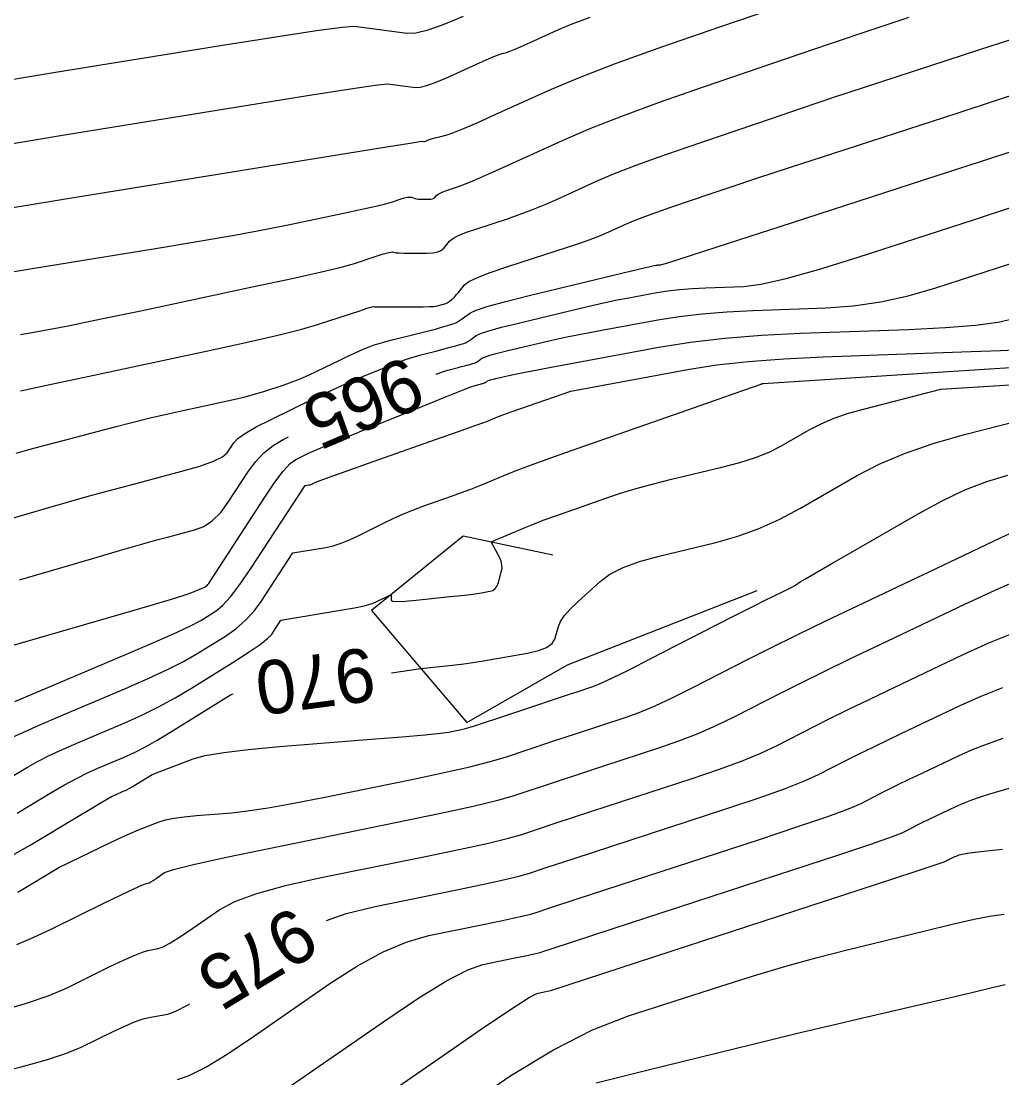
# Model space of a CAD drawing. Extents: x 2175772 to 2185556, y 721391 to 722853.
# Drawn here: x 2178632.3 to 2178683.6, y 721837.5 to 721892.9 of the extents above; entities that cross this region are included whole.
import ezdxf

# ---------------------------------------------------------------- set-up
doc = ezdxf.new("R2010")
doc.units = 0
for name, color, linetype in [('DT_X_Contour_Major', 7, 'Continuous'), ('DT_X_Contour_Minor', 7, 'Continuous'), ('SV_X_Break_Lines', 7, 'Continuous')]:
    doc.layers.add(name, color=color, linetype=linetype)

msp = doc.modelspace()

# ---------------------------------------------------------------- linework, layer by layer
at = {"layer": 'DT_X_Contour_Major'}
for points in [[(2178630.08, 721879.492), (2178632.733, 721879.933), (2178639.3, 721880.999), (2178641.587, 721881.377), (2178643.523, 721881.711), (2178645.106, 721882.002), (2178646.338, 721882.248), (2178649.155, 721882.848), (2178650.103, 721883.053), (2178650.836, 721883.217), (2178651.353, 721883.342), (2178651.655, 721883.426), (2178652.172, 721883.596), (2178652.35, 721883.65), (2178652.499, 721883.681), (2178652.616, 721883.691), (2178652.703, 721883.68), (2178652.895, 721883.62), (2178652.973, 721883.6), (2178653.065, 721883.586), (2178653.169, 721883.578), (2178653.285, 721883.575), (2178653.614, 721883.576), (2178653.727, 721883.582), (2178653.818, 721883.6), (2178653.888, 721883.63), (2178653.937, 721883.671), (2178654.039, 721883.798), (2178654.099, 721883.849), (2178654.204, 721883.905), (2178654.354, 721883.967), (2178654.549, 721884.034), (2178655.126, 721884.222), (2178655.457, 721884.347), (2178656.014, 721884.583), (2178656.798, 721884.929), (2178657.81, 721885.386), (2178660.81, 721886.75), (2178662.103, 721887.304), (2178663.734, 721887.94), (2178665.702, 721888.659), (2178668.007, 721889.462), (2178674.604, 721891.713), (2178676.882, 721892.488), (2178678.768, 721893.126)], [(2178653.993, 721874.416), (2178654.336, 721874.541), (2178654.617, 721874.628), (2178655.148, 721874.761), (2178655.332, 721874.807), (2178655.486, 721874.847), (2178655.611, 721874.88), (2178655.706, 721874.906), (2178655.919, 721874.966), (2178655.998, 721874.993), (2178656.074, 721875.026), (2178656.146, 721875.066), (2178656.215, 721875.114), (2178656.397, 721875.249), (2178656.533, 721875.312), (2178656.805, 721875.4), (2178657.215, 721875.511), (2178657.76, 721875.647), (2178659.397, 721876.042), (2178660.068, 721876.196), (2178660.853, 721876.363), (2178661.751, 721876.541), (2178662.763, 721876.731), (2178665.615, 721877.255), (2178666.729, 721877.433), (2178667.933, 721877.575), (2178669.227, 721877.68), (2178670.61, 721877.75), (2178674.42, 721877.886), (2178675.851, 721877.99), (2178677.288, 721878.199), (2178678.73, 721878.512), (2178680.177, 721878.931), (2178684.044, 721880.188)], [(2178651.666, 721858.763), (2178653.199, 721858.988), (2178655.021, 721859.179), (2178655.443, 721859.229), (2178655.927, 721859.298), (2178656.473, 721859.385), (2178657.082, 721859.49), (2178658.79, 721859.797), (2178659.359, 721859.929), (2178659.786, 721860.094), (2178660.07, 721860.293), (2178660.212, 721860.525), (2178660.402, 721861.191), (2178660.519, 721861.459), (2178660.727, 721861.764), (2178661.027, 721862.108), (2178661.419, 721862.488), (2178662.585, 721863.554), (2178663.106, 721863.937), (2178663.796, 721864.286), (2178664.655, 721864.601), (2178665.682, 721864.882), (2178668.647, 721865.588), (2178669.758, 721865.899), (2178670.866, 721866.303), (2178671.972, 721866.799), (2178673.076, 721867.389), (2178676.017, 721869.084), (2178677.198, 721869.696), (2178678.536, 721870.259), (2178680.03, 721870.776), (2178681.681, 721871.244), (2178689.749, 721873.317)], [(2178632.176, 721863.641), (2178636.07, 721864.777), (2178637.411, 721865.166), (2178638.512, 721865.482), (2178639.375, 721865.725), (2178639.998, 721865.894), (2178641.34, 721866.249), (2178641.828, 721866.439), (2178642.286, 721866.744), (2178642.715, 721867.164), (2178643.113, 721867.699), (2178644.135, 721869.277), (2178644.538, 721869.828), (2178644.98, 721870.296), (2178645.461, 721870.682), (2178645.981, 721870.985), (2178646.269, 721871.125)], [(2178648.253, 721845.79), (2178649.292, 721846.147), (2178650.801, 721846.518), (2178654.997, 721847.372), (2178656.417, 721847.666), (2178657.531, 721847.91), (2178658.339, 721848.103), (2178658.841, 721848.245), (2178659.771, 721848.556), (2178661.226, 721849.036), (2178669.172, 721851.633), (2178670.874, 721852.202), (2178672.251, 721852.691), (2178673.302, 721853.1), (2178674.028, 721853.429), (2178675.529, 721854.198), (2178676.15, 721854.512), (2178676.89, 721854.877), (2178677.747, 721855.292), (2178678.722, 721855.757), (2178681.478, 721857.067), (2178682.547, 721857.544), (2178683.686, 721857.995)], [(2178632.05, 721851.416), (2178633.873, 721852.51), (2178634.536, 721852.896), (2178635.157, 721853.234), (2178635.737, 721853.525), (2178636.275, 721853.768), (2178637.655, 721854.352), (2178638.193, 721854.597), (2178638.771, 721854.892), (2178639.391, 721855.239), (2178640.051, 721855.638), (2178643.226, 721857.615), (2178643.363, 721857.667)], [(2178662.38, 721837.287), (2178663.499, 721837.566), (2178665.029, 721837.944), (2178669.656, 721839.086), (2178671.375, 721839.507), (2178673.064, 721839.915), (2178674.721, 721840.309), (2178676.347, 721840.69), (2178680.64, 721841.687), (2178682.066, 721842.02), (2178683.123, 721842.27), (2178683.81, 721842.439)], [(2178630.678, 721837.737), (2178632.273, 721838.124), (2178633.592, 721838.488), (2178634.637, 721838.831), (2178635.406, 721839.152), (2178637.091, 721839.977), (2178637.686, 721840.256), (2178638.208, 721840.473), (2178638.658, 721840.627), (2178639.034, 721840.72), (2178639.941, 721840.885), (2178640.37, 721841.03), (2178640.979, 721841.343), (2178641.107, 721841.421)]]:
    msp.add_lwpolyline(points, dxfattribs=at)
at = {"layer": 'DT_X_Contour_Minor'}
for points in [[(2178631.516, 721883.086), (2178635.333, 721883.715), (2178651.302, 721886.306), (2178652.745, 721886.539), (2178653.232, 721886.615), (2178653.359, 721886.599), (2178653.381, 721886.6), (2178653.411, 721886.607), (2178653.45, 721886.621), (2178653.498, 721886.641), (2178653.637, 721886.704), (2178653.705, 721886.73), (2178653.806, 721886.76), (2178653.938, 721886.796), (2178654.103, 721886.836), (2178654.586, 721886.951), (2178654.881, 721887.05), (2178655.403, 721887.263), (2178656.154, 721887.59), (2178657.132, 721888.03), (2178660.044, 721889.354), (2178661.415, 721889.93), (2178663.341, 721890.665), (2178665.823, 721891.559), (2178668.861, 721892.611), (2178682.751, 721897.348)], [(2178630.69, 721889.673), (2178633.959, 721890.212), (2178642.71, 721891.632), (2178645.608, 721892.095), (2178647.739, 721892.418), (2178649.102, 721892.601), (2178649.699, 721892.644), (2178650.775, 721892.506), (2178652.467, 721892.281), (2178652.938, 721892.299), (2178653.589, 721892.453), (2178654.42, 721892.745), (2178655.431, 721893.173)], [(2178631.103, 721886.38), (2178634.646, 721886.963), (2178644.13, 721888.503), (2178647.256, 721889.007), (2178649.52, 721889.362), (2178650.924, 721889.57), (2178651.466, 721889.63), (2178652.382, 721889.511), (2178652.913, 721889.44), (2178653.162, 721889.45), (2178653.509, 721889.534), (2178653.955, 721889.692), (2178654.501, 721889.923), (2178656.087, 721890.639), (2178656.618, 721890.876), (2178657.023, 721891.052), (2178657.301, 721891.165), (2178657.452, 721891.217), (2178657.687, 721891.272), (2178657.83, 721891.321), (2178658.084, 721891.424), (2178658.448, 721891.583), (2178658.923, 721891.796), (2178660.337, 721892.44), (2178661.036, 721892.731), (2178662.071, 721893.122)], [(2178632.236, 721876.492), (2178633.319, 721876.682), (2178634.728, 721876.953), (2178636.463, 721877.305), (2178638.525, 721877.738), (2178644.457, 721879.001), (2178646.454, 721879.432), (2178647.998, 721879.778), (2178649.087, 721880.04), (2178649.722, 721880.217), (2178650.811, 721880.577), (2178651.174, 721880.693), (2178651.446, 721880.772), (2178651.626, 721880.814), (2178651.716, 721880.819), (2178651.833, 721880.783), (2178651.914, 721880.771), (2178652.071, 721880.762), (2178652.302, 721880.757), (2178652.607, 721880.756), (2178653.523, 721880.758), (2178653.837, 721880.775), (2178654.091, 721880.825), (2178654.286, 721880.908), (2178654.422, 721881.024), (2178654.706, 721881.377), (2178654.875, 721881.518), (2178655.168, 721881.674), (2178655.585, 721881.846), (2178656.126, 721882.034), (2178657.736, 721882.557), (2178658.357, 721882.771), (2178659.012, 721883.02), (2178659.702, 721883.305), (2178660.427, 721883.625), (2178662.406, 721884.525), (2178663.259, 721884.89), (2178664.335, 721885.309), (2178665.633, 721885.784), (2178667.154, 721886.313), (2178671.506, 721887.798), (2178673.141, 721888.353), (2178674.785, 721888.903), (2178676.437, 721889.45), (2178678.096, 721889.993), (2178682.532, 721891.435), (2178684.055, 721891.931)], [(2178632.232, 721873.544), (2178633.775, 721873.878), (2178635.821, 721874.315), (2178641.949, 721875.619), (2178644.037, 721876.073), (2178645.707, 721876.456), (2178646.958, 721876.768), (2178647.79, 721877.009), (2178649.997, 721877.737), (2178650.393, 721877.863), (2178650.636, 721877.937), (2178650.728, 721877.959), (2178650.771, 721877.945), (2178650.841, 721877.941), (2178651.021, 721877.938), (2178651.708, 721877.937), (2178652.915, 721877.939), (2178653.321, 721877.942), (2178653.634, 721877.95), (2178653.855, 721877.963), (2178653.983, 721877.981), (2178654.39, 721878.084), (2178654.512, 721878.119), (2178654.546, 721878.131), (2178654.586, 721878.152), (2178654.631, 721878.18), (2178654.681, 721878.215), (2178654.821, 721878.321), (2178654.882, 721878.374), (2178654.96, 721878.454), (2178655.055, 721878.562), (2178655.166, 721878.697), (2178655.484, 721879.094), (2178655.712, 721879.264), (2178656.158, 721879.478), (2178656.822, 721879.735), (2178657.704, 721880.035), (2178660.345, 721880.893), (2178661.257, 721881.195), (2178662.011, 721881.457), (2178662.607, 721881.68), (2178663.045, 721881.863), (2178664.003, 721882.299), (2178664.416, 721882.475), (2178664.936, 721882.679), (2178665.564, 721882.908), (2178666.3, 721883.164), (2178668.407, 721883.883), (2178669.401, 721884.217), (2178670.802, 721884.681), (2178672.612, 721885.274), (2178674.829, 721885.996), (2178681.287, 721888.096), (2178683.505, 721888.817), (2178685.317, 721889.409)], [(2178631.995, 721870.268), (2178632.742, 721870.476), (2178633.586, 721870.705), (2178634.528, 721870.956), (2178637.166, 721871.653), (2178638.127, 721871.901), (2178639.028, 721872.125), (2178639.872, 721872.323), (2178640.657, 721872.497), (2178642.672, 721872.926), (2178643.383, 721873.083), (2178644.005, 721873.233), (2178644.538, 721873.376), (2178644.982, 721873.511), (2178646.047, 721873.863), (2178646.454, 721874.006), (2178646.873, 721874.171), (2178647.306, 721874.358), (2178647.753, 721874.567), (2178648.962, 721875.154), (2178649.377, 721875.354), (2178649.717, 721875.515), (2178649.981, 721875.635), (2178650.17, 721875.716), (2178650.571, 721875.879), (2178650.758, 721875.946), (2178651.021, 721876.027), (2178651.358, 721876.12), (2178651.771, 721876.227), (2178652.969, 721876.527), (2178653.385, 721876.632), (2178653.734, 721876.722), (2178654.016, 721876.797), (2178654.231, 721876.856), (2178654.714, 721876.992), (2178654.892, 721877.052), (2178655.063, 721877.127), (2178655.227, 721877.218), (2178655.384, 721877.325), (2178655.793, 721877.632), (2178656.101, 721877.774), (2178656.718, 721877.972), (2178657.643, 721878.224), (2178658.876, 721878.532), (2178663.796, 721879.719), (2178664.676, 721879.93), (2178665.216, 721880.059), (2178665.418, 721880.106), (2178665.503, 721880.122), (2178665.537, 721880.127), (2178665.573, 721880.132), (2178665.612, 721880.135), (2178665.654, 721880.137), (2178665.768, 721880.141), (2178666.191, 721880.268), (2178667.374, 721880.644), (2178669.316, 721881.271), (2178672.018, 721882.148), (2178680.237, 721884.82), (2178683.058, 721885.738), (2178685.357, 721886.488)], [(2178630.957, 721866.627), (2178633.707, 721867.429), (2178634.741, 721867.727), (2178635.781, 721868.02), (2178636.827, 721868.306), (2178637.878, 721868.588), (2178640.688, 721869.33), (2178641.627, 721869.598), (2178642.334, 721869.847), (2178642.81, 721870.077), (2178643.055, 721870.286), (2178643.401, 721870.82), (2178643.618, 721871.045), (2178644.009, 721871.321), (2178644.576, 721871.647), (2178645.317, 721872.024), (2178647.526, 721873.096), (2178648.314, 721873.474), (2178649.021, 721873.802), (2178649.647, 721874.08), (2178650.192, 721874.31), (2178651.537, 721874.855), (2178652.019, 721875.045), (2178652.456, 721875.203), (2178652.847, 721875.33), (2178653.194, 721875.427), (2178654.058, 721875.644), (2178654.358, 721875.72), (2178654.61, 721875.785), (2178654.813, 721875.838), (2178654.968, 721875.881), (2178655.317, 721875.979), (2178655.445, 721876.022), (2178655.568, 721876.076), (2178655.686, 721876.142), (2178655.8, 721876.219), (2178656.095, 721876.441), (2178656.317, 721876.543), (2178656.762, 721876.686), (2178657.429, 721876.868), (2178658.318, 721877.089), (2178660.987, 721877.734), (2178661.932, 721877.957), (2178662.764, 721878.146), (2178663.484, 721878.3), (2178664.091, 721878.419), (2178665.559, 721878.688), (2178666.133, 721878.78), (2178666.753, 721878.853), (2178667.419, 721878.908), (2178668.132, 721878.943), (2178670.094, 721879.014), (2178671.021, 721879.129), (2178672.331, 721879.421), (2178674.023, 721879.892), (2178676.098, 721880.54), (2178682.14, 721882.504), (2178684.214, 721883.179)], [(2178631.428, 721860.095), (2178633.006, 721860.542), (2178637.525, 721861.86), (2178639.026, 721862.3), (2178640.139, 721862.631), (2178640.863, 721862.854), (2178641.2, 721862.969), (2178641.709, 721863.185), (2178641.876, 721863.26), (2178641.914, 721863.281), (2178641.977, 721863.32), (2178642.005, 721863.344), (2178642.042, 721863.387), (2178642.087, 721863.448), (2178642.141, 721863.527), (2178642.664, 721864.329), (2178645.025, 721867.975), (2178645.546, 721868.746), (2178645.99, 721869.332), (2178646.356, 721869.732), (2178646.645, 721869.946), (2178647.312, 721870.27), (2178647.682, 721870.438), (2178648.293, 721870.698), (2178649.145, 721871.051), (2178650.237, 721871.497), (2178653.469, 721872.808), (2178654.539, 721873.241), (2178655.325, 721873.555), (2178655.825, 721873.751), (2178656.041, 721873.828), (2178656.237, 721873.878), (2178656.305, 721873.895), (2178656.408, 721873.922), (2178656.443, 721873.931), (2178656.522, 721873.954), (2178656.551, 721873.963), (2178656.579, 721873.976), (2178656.606, 721873.99), (2178656.631, 721874.008), (2178656.698, 721874.058), (2178656.749, 721874.081), (2178656.849, 721874.114), (2178657, 721874.155), (2178657.202, 721874.205), (2178657.807, 721874.351), (2178658.204, 721874.435), (2178658.941, 721874.579), (2178660.018, 721874.782), (2178661.436, 721875.044), (2178665.671, 721875.821), (2178667.325, 721876.086), (2178669.113, 721876.296), (2178671.034, 721876.453), (2178673.089, 721876.556), (2178678.746, 721876.759), (2178680.681, 721876.851), (2178682.245, 721876.976), (2178683.436, 721877.133), (2178684.256, 721877.323)], [(2178631.934, 721857.267), (2178637.775, 721859.74), (2178639.255, 721860.374), (2178640.398, 721860.88), (2178641.203, 721861.259), (2178641.672, 721861.509), (2178642.471, 721862.007), (2178642.809, 721862.286), (2178643.225, 721862.751), (2178643.718, 721863.401), (2178644.289, 721864.237), (2178647.133, 721868.572), (2178647.338, 721868.606), (2178647.384, 721868.616), (2178647.433, 721868.632), (2178647.487, 721868.653), (2178647.544, 721868.68), (2178647.701, 721868.76), (2178647.917, 721868.844), (2178648.448, 721869.037), (2178649.292, 721869.338), (2178650.45, 721869.747), (2178653.958, 721870.983), (2178655.123, 721871.395), (2178655.986, 721871.702), (2178656.547, 721871.905), (2178656.807, 721872.003), (2178657.096, 721872.127), (2178657.262, 721872.192), (2178657.54, 721872.294), (2178657.93, 721872.434), (2178658.434, 721872.612), (2178661.049, 721873.528), (2178667.272, 721874.671), (2178668.71, 721874.895), (2178670.358, 721875.077), (2178672.214, 721875.217), (2178674.28, 721875.316), (2178680.067, 721875.523), (2178682.027, 721875.595), (2178683.568, 721875.656), (2178684.689, 721875.705)], [(2178631.691, 721855.338), (2178632.318, 721855.629), (2178633.202, 721856.02), (2178634.344, 721856.509), (2178637.735, 721857.944), (2178638.92, 721858.46), (2178639.93, 721858.931), (2178640.767, 721859.357), (2178641.429, 721859.737), (2178642.964, 721860.693), (2178643.512, 721861.075), (2178644.006, 721861.503), (2178644.446, 721861.979), (2178644.831, 721862.5), (2178646.5, 721865.044), (2178648.219, 721865.333), (2178648.603, 721865.418), (2178649.02, 721865.551), (2178649.468, 721865.731), (2178649.949, 721865.958), (2178651.273, 721866.627), (2178651.776, 721866.87), (2178652.291, 721867.099), (2178652.818, 721867.313), (2178653.356, 721867.513), (2178654.809, 721868.025), (2178655.332, 721868.212), (2178655.812, 721868.392), (2178656.248, 721868.563), (2178656.641, 721868.725), (2178657.631, 721869.147), (2178658.192, 721869.368), (2178659.131, 721869.715), (2178660.449, 721870.188), (2178662.146, 721870.786), (2178667.175, 721872.549), (2178668.827, 721873.128), (2178670.01, 721873.542), (2178670.724, 721873.791), (2178670.969, 721873.876), (2178671.008, 721873.886), (2178671.017, 721873.889), (2178671.025, 721873.892), (2178671.031, 721873.895), (2178671.047, 721873.904), (2178671.061, 721873.911), (2178671.069, 721873.914), (2178671.078, 721873.916), (2178671.122, 721873.928), (2178683.523, 721874.721), (2178685.9, 721874.867)], [(2178631.367, 721853.089), (2178632.598, 721853.827), (2178633.114, 721854.117), (2178633.737, 721854.432), (2178634.47, 721854.772), (2178635.31, 721855.138), (2178637.695, 721856.148), (2178638.584, 721856.546), (2178639.462, 721856.981), (2178640.33, 721857.455), (2178641.187, 721857.966), (2178643.457, 721859.38), (2178644.215, 721859.864), (2178644.787, 721860.256), (2178645.173, 721860.556), (2178645.372, 721860.763), (2178645.867, 721861.517), (2178649.1, 721862.059), (2178649.728, 721862.171), (2178650.226, 721862.277), (2178650.593, 721862.375), (2178650.831, 721862.466), (2178651.638, 721862.873), (2178651.637, 721862.566), (2178651.719, 721862.517), (2178651.967, 721862.502), (2178652.38, 721862.521), (2178652.957, 721862.573), (2178654.719, 721862.758), (2178655.318, 721862.822), (2178655.792, 721862.876), (2178656.144, 721862.921), (2178656.371, 721862.956), (2178656.813, 721863.035), (2178656.965, 721863.086), (2178657.09, 721863.18), (2178657.188, 721863.317), (2178657.259, 721863.497), (2178657.412, 721864.033), (2178657.45, 721864.231), (2178657.449, 721864.424), (2178657.411, 721864.61), (2178657.333, 721864.791), (2178656.882, 721865.621), (2178658.668, 721866.382), (2178659.095, 721866.557), (2178659.612, 721866.756), (2178660.217, 721866.979), (2178660.911, 721867.226), (2178662.881, 721867.917), (2178663.651, 721868.173), (2178664.484, 721868.423), (2178665.378, 721868.667), (2178666.335, 721868.905), (2178668.969, 721869.532), (2178669.903, 721869.778), (2178670.728, 721870.045), (2178671.445, 721870.333), (2178672.054, 721870.642), (2178673.532, 721871.494), (2178674.126, 721871.802), (2178674.798, 721872.085), (2178675.55, 721872.345), (2178676.379, 721872.58), (2178680.436, 721873.622), (2178687.124, 721874.05)], [(2178631.808, 721849.216), (2178632.732, 721849.743), (2178635.148, 721851.192), (2178635.959, 721851.675), (2178636.577, 721852.037), (2178637.005, 721852.278), (2178637.241, 721852.398), (2178637.615, 721852.556), (2178637.761, 721852.622), (2178637.918, 721852.703), (2178638.085, 721852.797), (2178638.264, 721852.905), (2178639.125, 721853.441), (2178641.282, 721854.258), (2178641.911, 721854.43), (2178642.874, 721854.593), (2178644.171, 721854.749), (2178645.802, 721854.896), (2178650.596, 721855.28), (2178652.197, 721855.411), (2178653.405, 721855.518), (2178654.22, 721855.601), (2178654.641, 721855.659), (2178655.24, 721855.781), (2178655.533, 721855.853), (2178655.962, 721855.978), (2178656.526, 721856.156), (2178657.227, 721856.387), (2178659.276, 721857.073), (2178659.984, 721857.31), (2178660.571, 721857.506), (2178661.038, 721857.661), (2178661.385, 721857.775), (2178662.148, 721858.025), (2178662.557, 721858.187), (2178663.21, 721858.489), (2178664.107, 721858.929), (2178665.249, 721859.508), (2178668.621, 721861.238), (2178669.755, 721861.818), (2178670.629, 721862.263), (2178671.241, 721862.572), (2178671.593, 721862.745), (2178672.184, 721863.026), (2178672.39, 721863.126), (2178672.564, 721863.215), (2178672.707, 721863.293), (2178672.818, 721863.361), (2178673.071, 721863.528), (2178673.314, 721863.675), (2178673.854, 721863.991), (2178674.691, 721864.476), (2178675.824, 721865.13), (2178679.241, 721867.1), (2178680.497, 721867.78), (2178681.7, 721868.346), (2178682.852, 721868.795), (2178683.951, 721869.129)], [(2178632.083, 721847.271), (2178634.241, 721848.565), (2178636.98, 721849.886), (2178637.529, 721850.148), (2178638.003, 721850.365), (2178638.402, 721850.539), (2178638.725, 721850.669), (2178639.487, 721850.958), (2178639.823, 721851.059), (2178640.262, 721851.148), (2178640.802, 721851.223), (2178641.445, 721851.285), (2178643.294, 721851.433), (2178644.118, 721851.526), (2178645.206, 721851.693), (2178646.555, 721851.936), (2178648.167, 721852.253), (2178652.817, 721853.198), (2178654.425, 721853.536), (2178655.763, 721853.841), (2178656.832, 721854.113), (2178657.63, 721854.351), (2178660.065, 721855.166), (2178661.41, 721855.611), (2178663.904, 721856.427), (2178664.636, 721856.691), (2178665.47, 721857.039), (2178666.406, 721857.472), (2178667.444, 721857.988), (2178670.348, 721859.478), (2178671.525, 721860.073), (2178672.878, 721860.741), (2178674.408, 721861.483), (2178676.113, 721862.299), (2178680.896, 721864.57), (2178683.592, 721865.851), (2178684.27, 721866.174)], [(2178632.044, 721844.53), (2178632.896, 721844.893), (2178633.864, 721845.349), (2178636.6, 721846.69), (2178637.505, 721847.132), (2178638.166, 721847.45), (2178638.584, 721847.644), (2178638.759, 721847.716), (2178638.901, 721847.742), (2178638.969, 721847.764), (2178639.064, 721847.813), (2178639.187, 721847.889), (2178639.339, 721847.99), (2178639.78, 721848.296), (2178640.24, 721848.46), (2178641.289, 721848.724), (2178642.926, 721849.087), (2178645.153, 721849.55), (2178651.875, 721850.917), (2178654.151, 721851.389), (2178655.936, 721851.779), (2178657.23, 721852.088), (2178658.034, 721852.316), (2178660.146, 721853.023), (2178661.781, 721853.561), (2178662.792, 721853.892), (2178665.66, 721854.829), (2178666.715, 721855.195), (2178667.73, 721855.59), (2178668.705, 721856.015), (2178669.638, 721856.468), (2178672.075, 721857.718), (2178673.084, 721858.228), (2178674.284, 721858.819), (2178675.676, 721859.493), (2178677.258, 721860.249), (2178681.733, 721862.374), (2178683.273, 721863.093), (2178684.54, 721863.654)], [(2178631.041, 721841.021), (2178632.485, 721841.433), (2178633.683, 721841.843), (2178634.635, 721842.25), (2178636.845, 721843.334), (2178637.595, 721843.694), (2178638.187, 721843.961), (2178638.621, 721844.136), (2178638.897, 721844.218), (2178639.421, 721844.313), (2178639.67, 721844.397), (2178640.021, 721844.578), (2178640.476, 721844.856), (2178641.035, 721845.23), (2178642.662, 721846.357), (2178643.452, 721846.778), (2178644.601, 721847.199), (2178646.109, 721847.617), (2178647.977, 721848.034), (2178653.436, 721849.144), (2178655.284, 721849.527), (2178656.734, 721849.844), (2178657.785, 721850.095), (2178658.438, 721850.28), (2178660.228, 721850.879), (2178662.152, 721851.511), (2178667.416, 721853.231), (2178668.795, 721853.698), (2178669.99, 721854.14), (2178671.003, 721854.557), (2178671.833, 721854.948), (2178673.802, 721855.958), (2178674.617, 721856.37), (2178675.587, 721856.848), (2178676.711, 721857.392), (2178677.99, 721858.003), (2178681.605, 721859.72), (2178682.946, 721860.329), (2178684.255, 721860.866)], [(2178640.461, 721837.457), (2178641.071, 721837.663), (2178641.936, 721838.108), (2178643.054, 721838.79), (2178644.427, 721839.709), (2178648.426, 721842.478), (2178649.875, 721843.415), (2178651.225, 721844.148), (2178652.475, 721844.677), (2178653.625, 721845.003), (2178656.558, 721845.599), (2178657.551, 721845.805), (2178658.329, 721845.975), (2178658.894, 721846.11), (2178659.245, 721846.209), (2178659.895, 721846.427), (2178661.39, 721846.919), (2178670.928, 721850.035), (2178672.953, 721850.706), (2178674.511, 721851.241), (2178675.601, 721851.642), (2178676.222, 721851.909), (2178677.255, 721852.438), (2178677.683, 721852.655), (2178678.192, 721852.905), (2178678.782, 721853.191), (2178679.453, 721853.512), (2178681.351, 721854.413), (2178682.087, 721854.742), (2178682.871, 721855.052), (2178683.704, 721855.344)], [(2178646.123, 721836.949), (2178651.308, 721840.539), (2178653.087, 721841.733), (2178654.537, 721842.623), (2178655.658, 721843.207), (2178656.449, 721843.487), (2178658.119, 721843.826), (2178658.684, 721843.944), (2178659.127, 721844.041), (2178659.449, 721844.117), (2178659.648, 721844.174), (2178660.018, 721844.298), (2178663.265, 721845.36), (2178672.684, 721848.437), (2178675.033, 721849.209), (2178676.771, 721849.792), (2178677.899, 721850.185), (2178678.417, 721850.389), (2178678.982, 721850.679), (2178679.216, 721850.797), (2178679.495, 721850.934), (2178679.818, 721851.091), (2178681.224, 721851.759), (2178681.627, 721851.939), (2178682.056, 721852.109), (2178682.511, 721852.269), (2178682.994, 721852.419), (2178684.315, 721852.805)], [(2178647.819, 721834.189), (2178654.19, 721838.6), (2178656.299, 721840.052), (2178657.849, 721841.097), (2178658.841, 721841.737), (2178659.273, 721841.971), (2178659.817, 721842.082), (2178660.003, 721842.125), (2178660.052, 721842.138), (2178666.308, 721844.183), (2178674.44, 721846.839), (2178677.112, 721847.713), (2178679.032, 721848.342), (2178680.198, 721848.728), (2178680.611, 721848.869), (2178680.709, 721848.919), (2178680.75, 721848.939), (2178680.798, 721848.963), (2178680.854, 721848.99), (2178680.917, 721849.02), (2178681.097, 721849.106), (2178681.166, 721849.137), (2178681.24, 721849.166), (2178681.319, 721849.194), (2178681.403, 721849.22), (2178681.631, 721849.286), (2178681.822, 721849.32), (2178682.225, 721849.37), (2178682.839, 721849.437), (2178683.665, 721849.52)], [(2178655.511, 721836.001), (2178657.914, 721837.66), (2178660.143, 721839.01), (2178662.198, 721840.052), (2178664.079, 721840.785), (2178668.864, 721842.33), (2178670.626, 721842.884), (2178672.322, 721843.388), (2178673.954, 721843.842), (2178675.52, 721844.245), (2178679.61, 721845.254), (2178681.02, 721845.592), (2178682.18, 721845.849), (2178683.091, 721846.024), (2178683.754, 721846.117)]]:
    msp.add_lwpolyline(points, dxfattribs=at)
at = {"layer": 'SV_X_Break_Lines'}
msp.add_lwpolyline([(2178660.116, 721864.934), (2178655.411, 721865.933), (2178650.608, 721862.038), (2178655.599, 721856.163), (2178660.875, 721859.183), (2178670.812, 721863.075)], dxfattribs=at)

# ---------------------------------------------------------------- texts
at = {"layer": 'DT_X_Contour_Major'}
for s, rotation, p in [('965', 203.0787, (2178652.517, 721875.408)), ('970', 187.518, (2178650.588, 721860.115)), ('975', 211.4405, (2178646.582, 721846.616))]:
    msp.add_text(s, height=2.8, rotation=rotation, dxfattribs=at).set_placement(p)

doc.saveas('drawing.dxf')
